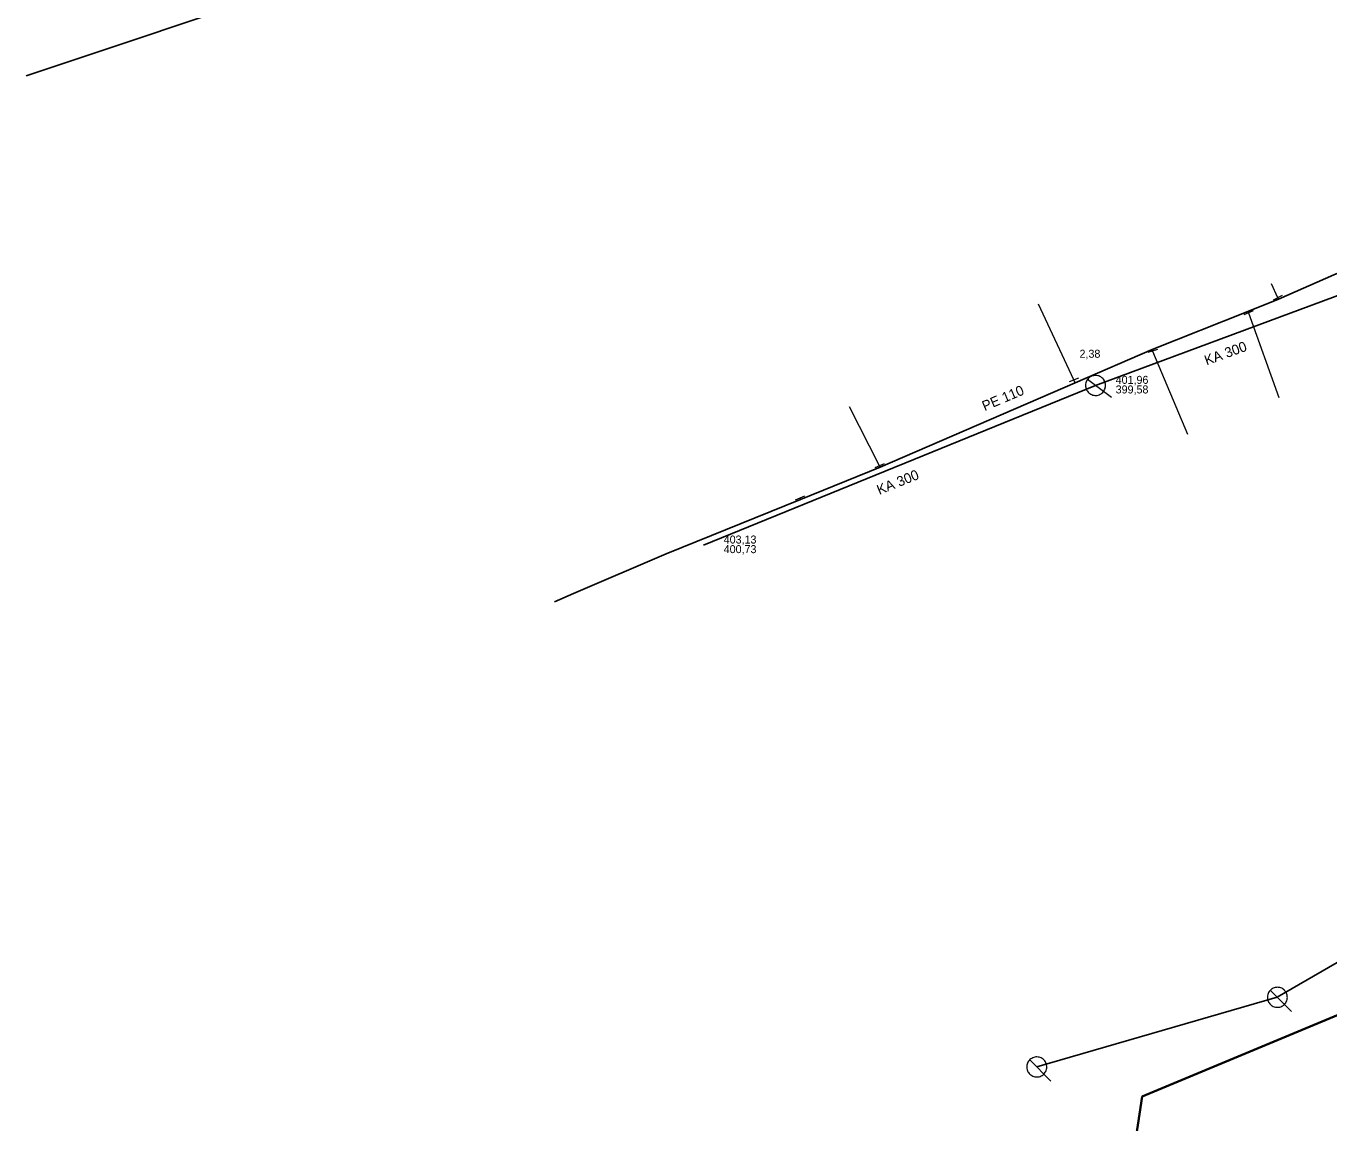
# Model space of a CAD drawing. Extents: x -809028 to -807737, y -990545 to -989489.
# Drawn here: x -808938.8 to -808808.6, y -990116 to -990006.3 of the extents above; entities that cross this region are included whole.
import ezdxf

# ---------------------------------------------------------------- set-up
doc = ezdxf.new("R2010")
doc.units = 0
doc.header["$LTSCALE"] = 0.32
for name, color, linetype, lineweight in [('1', 7, 'Continuous', 13), ('13', 7, 'Continuous', 13), ('14', 7, 'Continuous', 25), ('17', 7, 'Continuous', 25), ('22', 7, 'Continuous', 13), ('34', 7, 'Continuous', 13)]:
    doc.layers.add(name, color=color, linetype=linetype, lineweight=lineweight)

msp = doc.modelspace()

# ---------------------------------------------------------------- linework, layer by layer
at = {"layer": '13'}
for p, q in [((-808813.69, -990033.51), (-808814.322, -990032.113)), ((-808834.069, -990041.719), (-808837.627, -990034.147)), ((-808816.619, -990035.02), (-808813.59, -990043.465)), ((-808826.199, -990038.829), (-808822.714, -990047.127)), ((-808853.509, -990050.3), (-808856.504, -990044.401))]:
    msp.add_line(p, q, dxfattribs=at)
at = {"layer": '14'}
for p, q in [((-808831.909, -990042.27), (-808805.459, -990032.46)), ((-808871.099, -990058.239), (-808831.909, -990042.27)), ((-808813.733, -990103.458), (-808802.904, -990097.146)), ((-808837.785, -990110.423), (-808813.733, -990103.458))]:
    msp.add_line(p, q, dxfattribs=at)
at = {"layer": '14', "lineweight": 13}
for p, q in [((-808813.62, -990033.649), (-808813.69, -990033.51)), ((-808816.68, -990034.879), (-808816.619, -990035.02)), ((-808826.25, -990038.68), (-808826.199, -990038.829)), ((-808833.949, -990042.01), (-808834.069, -990041.719)), ((-808853.449, -990050.44), (-808853.509, -990050.3)), ((-808861.41, -990053.69), (-808861.469, -990053.55))]:
    msp.add_line(p, q, dxfattribs=at)
at = {"layer": '17'}
for points in [[(-808938.839, -990011.319), (-808911.964, -990002.307), (-808886.164, -989991.55), (-808880.377, -989989.651), (-808879.513, -989989.281), (-808826.709, -989966.719)], [(-808759.931, -990010.868), (-808759.967, -990010.886), (-808765.697, -990013.552), (-808773.489, -990017.19), (-808786.66, -990022.489), (-808787.14, -990022.68), (-808797.739, -990026.92), (-808808.079, -990031.21), (-808813.62, -990033.649), (-808816.68, -990034.879), (-808826.25, -990038.68), (-808833.949, -990042.01), (-808853.449, -990050.44), (-808861.41, -990053.69), (-808874.829, -990059.1), (-808884.109, -990063.09), (-808885.989, -990063.91)]]:
    msp.add_lwpolyline(points, dxfattribs=at)
at = {"layer": '17', "lineweight": 35}
msp.add_lwpolyline([(-808750.059, -990081.211), (-808827.237, -990113.386), (-808831.41, -990140.956), (-808863.271, -990184.294), (-808913.198, -990187.432)], dxfattribs=at)
at = {"layer": '22'}
for p, q in [((-808830.32, -990043.485), (-808832.702, -990041.662)), ((-808812.315, -990104.869), (-808814.441, -990102.752)), ((-808836.367, -990111.834), (-808838.493, -990109.717))]:
    msp.add_line(p, q, dxfattribs=at)
for points in [[(-808831.3, -990041.476), (-808831.39, -990041.414), (-808831.487, -990041.363), (-808831.59, -990041.322), (-808831.694, -990041.293), (-808831.803, -990041.275), (-808831.912, -990041.27), (-808832.022, -990041.276), (-808832.129, -990041.295), (-808832.235, -990041.325), (-808832.336, -990041.366), (-808832.432, -990041.418), (-808832.522, -990041.481), (-808832.605, -990041.553), (-808832.679, -990041.633), (-808832.744, -990041.722), (-808832.799, -990041.816), (-808832.844, -990041.916), (-808832.877, -990042.021), (-808832.898, -990042.128), (-808832.908, -990042.236), (-808832.905, -990042.347), (-808832.891, -990042.455), (-808832.864, -990042.562), (-808832.827, -990042.664), (-808832.779, -990042.762), (-808832.719, -990042.854), (-808832.65, -990042.94), (-808832.573, -990043.017), (-808832.487, -990043.085), (-808832.394, -990043.143), (-808832.296, -990043.192), (-808832.193, -990043.228), (-808832.087, -990043.254), (-808831.978, -990043.268), (-808831.868, -990043.269), (-808831.76, -990043.259), (-808831.652, -990043.237), (-808831.548, -990043.203), (-808831.448, -990043.158), (-808831.354, -990043.102), (-808831.266, -990043.037), (-808831.186, -990042.962), (-808831.115, -990042.878), (-808831.053, -990042.788), (-808831.002, -990042.691), (-808830.961, -990042.59), (-808830.932, -990042.485), (-808830.914, -990042.376), (-808830.908, -990042.267), (-808830.914, -990042.158), (-808830.932, -990042.05), (-808830.963, -990041.944), (-808831.003, -990041.843), (-808831.056, -990041.747), (-808831.118, -990041.657), (-808831.19, -990041.574), (-808831.271, -990041.5)], [(-808813.026, -990102.749), (-808813.108, -990102.677), (-808813.197, -990102.613), (-808813.293, -990102.56), (-808813.393, -990102.517), (-808813.499, -990102.485), (-808813.606, -990102.466), (-808813.716, -990102.458), (-808813.825, -990102.462), (-808813.933, -990102.478), (-808814.039, -990102.506), (-808814.141, -990102.545), (-808814.239, -990102.596), (-808814.33, -990102.656), (-808814.414, -990102.727), (-808814.49, -990102.806), (-808814.556, -990102.892), (-808814.614, -990102.986), (-808814.661, -990103.085), (-808814.695, -990103.189), (-808814.719, -990103.295), (-808814.731, -990103.405), (-808814.73, -990103.514), (-808814.718, -990103.623), (-808814.695, -990103.73), (-808814.659, -990103.833), (-808814.612, -990103.932), (-808814.555, -990104.026), (-808814.488, -990104.112), (-808814.412, -990104.191), (-808814.327, -990104.261), (-808814.237, -990104.322), (-808814.139, -990104.371), (-808814.037, -990104.41), (-808813.931, -990104.438), (-808813.822, -990104.454), (-808813.713, -990104.458), (-808813.604, -990104.45), (-808813.496, -990104.43), (-808813.392, -990104.398), (-808813.291, -990104.355), (-808813.195, -990104.302), (-808813.106, -990104.238), (-808813.024, -990104.164), (-808812.952, -990104.083), (-808812.888, -990103.994), (-808812.835, -990103.899), (-808812.792, -990103.798), (-808812.76, -990103.692), (-808812.741, -990103.585), (-808812.732, -990103.476), (-808812.736, -990103.366), (-808812.752, -990103.258), (-808812.78, -990103.152), (-808812.819, -990103.05), (-808812.869, -990102.953), (-808812.93, -990102.861), (-808813, -990102.777)], [(-808837.078, -990109.714), (-808837.16, -990109.642), (-808837.249, -990109.578), (-808837.345, -990109.525), (-808837.445, -990109.482), (-808837.551, -990109.45), (-808837.658, -990109.431), (-808837.768, -990109.423), (-808837.877, -990109.427), (-808837.985, -990109.443), (-808838.091, -990109.471), (-808838.193, -990109.51), (-808838.291, -990109.561), (-808838.382, -990109.621), (-808838.466, -990109.692), (-808838.542, -990109.771), (-808838.608, -990109.857), (-808838.666, -990109.951), (-808838.713, -990110.05), (-808838.747, -990110.154), (-808838.771, -990110.26), (-808838.783, -990110.37), (-808838.782, -990110.479), (-808838.77, -990110.588), (-808838.747, -990110.695), (-808838.711, -990110.798), (-808838.664, -990110.897), (-808838.607, -990110.991), (-808838.54, -990111.077), (-808838.464, -990111.156), (-808838.379, -990111.226), (-808838.289, -990111.287), (-808838.191, -990111.336), (-808838.089, -990111.375), (-808837.983, -990111.403), (-808837.874, -990111.419), (-808837.765, -990111.423), (-808837.656, -990111.415), (-808837.548, -990111.395), (-808837.444, -990111.363), (-808837.343, -990111.32), (-808837.247, -990111.267), (-808837.158, -990111.203), (-808837.076, -990111.129), (-808837.004, -990111.048), (-808836.94, -990110.959), (-808836.887, -990110.864), (-808836.844, -990110.763), (-808836.812, -990110.657), (-808836.793, -990110.55), (-808836.784, -990110.441), (-808836.788, -990110.331), (-808836.804, -990110.223), (-808836.832, -990110.117), (-808836.871, -990110.015), (-808836.921, -990109.918), (-808836.982, -990109.826), (-808837.052, -990109.742)]]:
    msp.add_lwpolyline(points, close=True, dxfattribs=at)
at = {"layer": '34'}
for p, q in [((-808813.243, -990033.285), (-808814.137, -990033.733)), ((-808816.159, -990034.822), (-808817.078, -990035.216)), ((-808825.724, -990038.67), (-808826.673, -990038.986)), ((-808833.607, -990041.527), (-808834.531, -990041.909)), ((-808853.049, -990050.102), (-808853.968, -990050.496)), ((-808861.009, -990053.352), (-808861.928, -990053.746))]:
    msp.add_line(p, q, dxfattribs=at)

# ---------------------------------------------------------------- texts
at = {"layer": '1'}
msp.add_text('2,38', height=0.8, dxfattribs=at).set_placement((-808833.509, -990039.501))
for s, rotation, p in [('KA 300', 20, (-808820.806, -990040.269)), ('PE 110', 23, (-808842.994, -990044.845)), ('KA 300', 22, (-808853.533, -990053.225))]:
    msp.add_text(s, height=1, rotation=rotation, dxfattribs=at).set_placement(p)
at = {"layer": '14'}
for s, p in [('401,96', (-808829.895, -990042.11)), ('399,58', (-808829.895, -990043.07)), ('403,13', (-808869.085, -990058.08)), ('400,73', (-808869.085, -990059.04))]:
    msp.add_text(s, height=0.8, dxfattribs=at).set_placement(p)

doc.saveas('drawing.dxf')
